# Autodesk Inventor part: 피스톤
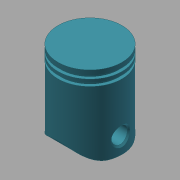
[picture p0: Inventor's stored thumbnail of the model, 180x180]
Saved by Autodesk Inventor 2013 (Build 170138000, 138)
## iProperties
Created: 2017-05
Part Number: 피스톤
Material: 일반
Document SubType Name: Modeling
Designer: mduedu
Density: 1 g/cm^3
Mass: 32.361 g
Surface Area: 150.47 cm^2
Volume: 32.361 cm^3
Author: mduedu
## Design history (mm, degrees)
sketch "스케치1"
  geometry: L1 (0, 0)-(20, 0); L2 (20, -50)-(15, -50); L3 (15, -50)-(15, -5); L4 (15, -5)-(0, -5); L5 (0, -5)-(0, 0); L6 (20, -3)-(18, -3); L7 (18, -3)-(18, -5); L8 (18, -5)-(20, -5); L9 (20, -7)-(18, -7); L10 (18, -7)-(18, -9); L11 (18, -9)-(20, -9); L12 (20, 0)-(20, -3); L13 (20, -5)-(20, -7); L14 (20, -9)-(20, -50); L15 (0, -60)-(0, 10) reference
  constraints: 28 end point, 10 parallel, 5 perpendicular, 4 collinear, 3 horizontal
  dimensions: "d0" = 20 distance of L1.start L1.end; "d1" = 2 distance of L6.start L6.end; "d2" = 2 distance of L6.end L7.end; "d3" = 2 distance of L8.end L9.start; "d4" = 3 distance of L1.end L6.start; "d5" = 5 distance of L2.start L2.end; "d6" = 50 distance between parallel lines of L1 L2; "d7" = 5 distance of L4.end L1.start
revolve "회전1" sketch "스케치1" stored, may be unused: angle "d8" = 90 deg
fillet "모깎기1" dims "d9" = 1
sketch "스케치2"
  geometry: L1 (-50, 15)-(-50, -15) reference; C1 r 10 at (-40, 0); 1 further point
  constraints: 1 centre point, 1 horizontal alignment
  dimensions: "d10" = 20 diameter of C1; "d11" = 10 distance from line of C1.centre L1
extrude "돌출1" join sketch "스케치2" stored distance "d12" = 10; taper "d13" = 0 deg
sketch "스케치3"
  geometry: L1 (0, -20)-(-3, -20) reference; L2 (-3, -20)-(-3, -18) reference; L3 (-3, -18)-(-5, -18) reference; L4 (-5, -18)-(-5, -20) reference; L5 (-5, -20)-(-7, -20) reference; L6 (-7, -20)-(-7, -18) reference; L7 (-7, -18)-(-9, -18) reference; L8 (-9, -18)-(-9, -20) reference; L9 (-9, -20)-(-50, -20) reference; L10 (-50, -20)-(-50, -15) reference; L11 (-50, -15)-(-6, -15) reference; L12 (-5, -14)-(-5, 14) reference; L13 (-6, 15)-(-50, 15) reference; L14 (-50, 15)-(-50, 20) reference; L15 (-50, 20)-(-9, 20) reference; L16 (-9, 20)-(-9, 18) reference; L17 (-9, 18)-(-7, 18) reference; L18 (-7, 18)-(-7, 20) reference; L19 (-7, 20)-(-5, 20) reference; L20 (-5, 20)-(-5, 18) reference; L21 (-5, 18)-(-3, 18) reference; L22 (-3, 18)-(-3, 20) reference; L23 (-3, 20)-(0, 20) reference; L24 (0, 20)-(0, -20) reference; C1 r 10 at (-40, 0) reference; C2 r 5 at (-40, 0); A1 r 1 centre (-6, -14) between (-6, -15) and (-5, -14) reference; A2 r 1 centre (-6, 14) between (-5, 14) and (-6, 15) reference; 1 further point
  constraints: 1 centre point, 1 coincident
  dimensions: "d15" = 10 diameter of C2
extrude "돌출2" cut sketch "스케치3" stored distance "d16" = 10; taper "d17" = 0 deg
sketch "스케치4"
  geometry: L1 (15, -50)-(-15, -50) reference; L2 (-15, -50)-(-20, -50) reference; L3 (-20, -50)-(-20, -45) reference; L4 (20, -45)-(20, -50) reference; L5 (20, -50)-(15, -50) reference; L6 (-15, -30)-(15, -30) reference; L7 (15, -30)-(15, -6) reference; L8 (14, -5)-(-14, -5) reference; L9 (-15, -6)-(-15, -30) reference; L10 (-20, -3)-(-20, 0) reference; L11 (-20, 0)-(20, 0) reference; L12 (20, 0)-(20, -3) reference; L13 (20, -3)-(18, -3) reference; L14 (18, -3)-(18, -5) reference; L15 (18, -5)-(20, -5) reference; L16 (20, -5)-(20, -7) reference; L17 (20, -7)-(18, -7) reference; L18 (18, -7)-(18, -9) reference; L19 (18, -9)-(20, -9) reference; L20 (-20, -9)-(-18, -9) reference; L21 (-18, -9)-(-18, -7) reference; L22 (-18, -7)-(-20, -7) reference; L23 (-20, -7)-(-20, -5) reference; L24 (-20, -5)-(-18, -5) reference; L25 (-18, -5)-(-18, -3) reference; L26 (-18, -3)-(-20, -3) reference; L27 (0, 0)-(0, -50); L28 (-5.698, -50)-(-5, -30); L29 (5.698, -50)-(5, -30); L30 (-5, -30)-(5, -30); L31 (-5.698, -50)-(5.698, -50); L32 (-20, -45)-(20, -45) reference; L33 (20, -9)-(20, -35) reference; L34 (20, -35)-(-20, -35) reference; L35 (-20, -35)-(-20, -9) reference; A1 r 1 centre (14, -6) between (15, -6) and (14, -5) reference; A2 r 1 centre (-14, -6) between (-14, -5) and (-15, -6) reference
  constraints: 10 end point, 2 point on line, 2 symmetric about line, 1 midpoint, 1 parallel, 1 perpendicular
  dimensions: "d18" = 2 deg angle of L27 L28; "d19" = 5 distance from line of L27 L28.end
extrude "돌출3" cut sketch "스케치4" stored distance "d20" = 20; taper "d21" = 0 deg
chamfer "모따기1" distance "d22" = 1; stored, may be unused: second distance "d23" = 2, angle "d24" = 45 deg
sketch "스케치5"
  geometry: L1 (-50, 0)-(-50, -15) reference; L2 (-50, 15)-(-50, 0) reference; L3 (-9, 20)-(-50, 20) reference; L4 (-50, 20)-(-50, -20) reference; L5 (-9, -20)-(-50, -20) reference; L6 (-42.483, -20)-(-50, -20); L7 (-50, -20)-(-50, -7); L8 (-42.483, 20)-(-50, 20); L9 (-50, 20)-(-50, 7); A1 r 15 centre (-35, 7) between (-42.483, 20) and (-50, 7); A2 r 15 centre (-35, -7) between (-42.483, -20) and (-50, -7); 1 further point
  constraints: 8 end point, 4 point on circle, 4 point on line, 2 centre point, 2 tangent, 1 collinear, 1 equal radius, 1 perpendicular
  dimensions: "d25" = 30 diameter of A1; "d26" = 7 vertical distance of A2.centre point (0, 0); "d27" = 7 vertical distance of point (0, 0) A1.centre (= d26)
extrude "돌출4" cut sketch "스케치5" stored distance "d28" = 20; taper "d29" = 0 deg
node "솔리드1"
node "절단 모서리 투영1"
node "절단 모서리 투영2"
